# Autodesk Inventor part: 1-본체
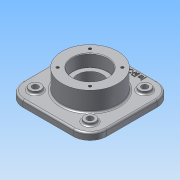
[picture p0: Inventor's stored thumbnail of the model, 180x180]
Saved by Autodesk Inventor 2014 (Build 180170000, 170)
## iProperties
Created: 2015-09
Part Number: 1-본체
Material: 알루미늄 6061
Document SubType Name: Modeling
Designer: study
Density: 2.71 g/cm^3
Appearance: 알루미늄 - 평지
Mass: 1465.21 g
Surface Area: 803.19 cm^2
Volume: 540.668 cm^3
Author: study
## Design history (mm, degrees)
sketch "스케치1"
  geometry: L1 (-75, -75)-(75, -75); L2 (75, -75)-(75, 75); L3 (75, 75)-(-75, 75); L4 (-75, 75)-(-75, -75); L5 (-75, -75)-(75, 75); L6 (75, -75)-(-75, 75); 1 further point
  constraints: 12 end point, 2 midpoint, 2 parallel, 2 perpendicular, 1 horizontal
  dimensions: "d0" = 150 distance of L2.end L3.end
extrude "돌출1" new body sketch "스케치1" distance "d1" = 12; taper "d2" = 0 deg
fillet "모깎기1" dims "d3" = 30
node "작업 평면1"
sketch "스케치2"
  geometry: C1 r 50 at (0, 0); 1 further point
  constraints: 1 centre point, 1 coincident
  dimensions: "d5" = 100 diameter of C1
extrude "돌출2" join sketch "스케치2" distance "d7" = 70; taper "d8" = 0 deg
sketch "스케치3"
  geometry: C1 r 50 at (0, 0) reference; C2 r 10 at (-49, 49); C3 r 10 at (49, 49); C4 r 10 at (-49, -49); C5 r 10 at (49, -49)
  constraints: 4 centre point, 3 equal radius, 2 horizontal alignment, 2 vertical alignment
  dimensions: "d45" = 20 diameter of C2; "d46" = 98 distance of C3.centre C2.centre; "d47" = 49 horizontal distance of C1.centre C2.centre; "d48" = 98 distance of C2.centre C4.centre; "d49" = 49 horizontal distance of C4.centre C1.centre
extrude "돌출3" join sketch "스케치3" distance "d10" = 5; taper "d11" = 0 deg
sketch "스케치7"
  geometry: C1 r 10 at (0, 0) reference; C2 r 10 at (98, 0) reference; C3 r 10 at (0, -98) reference; C4 r 10 at (98, -98) reference; 5 further points
  constraints: 4 coincident
hole "구멍4" sketch "스케치7" at (0, 0), (98, 0), (98, -98), (0, -98) diameter "d51" = 11; stored, may be unused: countersink angle "d55" = 90 deg, drill point angle "d57" = 0 deg; dims "d52" = 10, "d53" = 62, "d54" = 22, "d56" = 13
hole "구멍1" diameter "d18" = 45; stored, may be unused: countersink angle "d22" = 90 deg, drill point angle "d24" = 0 deg; dims "d16" = 10, "d17" = 10, "d19" = 6, "d20" = 62, "d21" = 22, "d23" = 80
hole "구멍2" diameter "d27" = 45; stored, may be unused: countersink angle "d31" = 90 deg, drill point angle "d33" = 0 deg; dims "d25" = 10, "d26" = 10, "d28" = 6, "d29" = 62, "d30" = 22, "d32" = 80
sketch "스케치5" dims "d34" = 82
  geometry: L1 (-28.991, -28.991)-(28.991, -28.991); L2 (28.991, -28.991)-(28.991, 28.991); L3 (28.991, 28.991)-(-28.991, 28.991); L4 (-28.991, 28.991)-(-28.991, -28.991); L5 (-28.991, -28.991)-(28.991, 28.991); L6 (28.991, -28.991)-(-28.991, 28.991); C1 r 50 at (0, 0) reference; 5 further points
  constraints: 12 end point, 5 coincident, 2 midpoint, 2 parallel, 2 perpendicular, 1 horizontal, 3 other
hole "구멍3" sketch "스케치5" at (-28.991, 28.991), (-28.991, -28.991), (28.991, -28.991), (28.991, 28.991) diameter "d35" = 4.917; stored, may be unused: countersink angle "d39" = 90 deg, drill point angle "d41" = 118 deg; dims "d36" = 10, "d37" = 62, "d38" = 22, "d40" = 13
node "작업 평면2"
sketch "스케치6"
  geometry: C1 r 50 at (0, 0) reference; 1 further point
  constraints: 1 vertical alignment, 1 other
  dimensions: "d42" = 65 distance of point (0, 65) C1.centre
feature "엠보싱1" sketch "스케치6" dims "d23" = 80, "d43" = 1, "d44" = 0
fillet "모깎기2" dims "d58" = 0.3
fillet "모깎기3" dims "d59" = 3
fillet "모깎기4" dims "d60" = 3
chamfer "모따기1" distance "d61" = 1; stored, may be unused: second distance "d62" = 2, angle "d63" = 45 deg
node "솔리드1"
mirror "대칭1"
other parameters: "d6" = 23
